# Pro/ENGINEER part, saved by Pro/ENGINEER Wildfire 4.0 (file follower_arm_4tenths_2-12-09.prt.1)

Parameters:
  METRIC = "NO"

Other parameters: PITCH, DRILL_DIAMETER, THREAD_DIAMETER, THREADS_PER_INCH, THREAD_DEPTH, THREAD_LENGTH, DRILL_POINT_ANGLE, DRILL_DEPTH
